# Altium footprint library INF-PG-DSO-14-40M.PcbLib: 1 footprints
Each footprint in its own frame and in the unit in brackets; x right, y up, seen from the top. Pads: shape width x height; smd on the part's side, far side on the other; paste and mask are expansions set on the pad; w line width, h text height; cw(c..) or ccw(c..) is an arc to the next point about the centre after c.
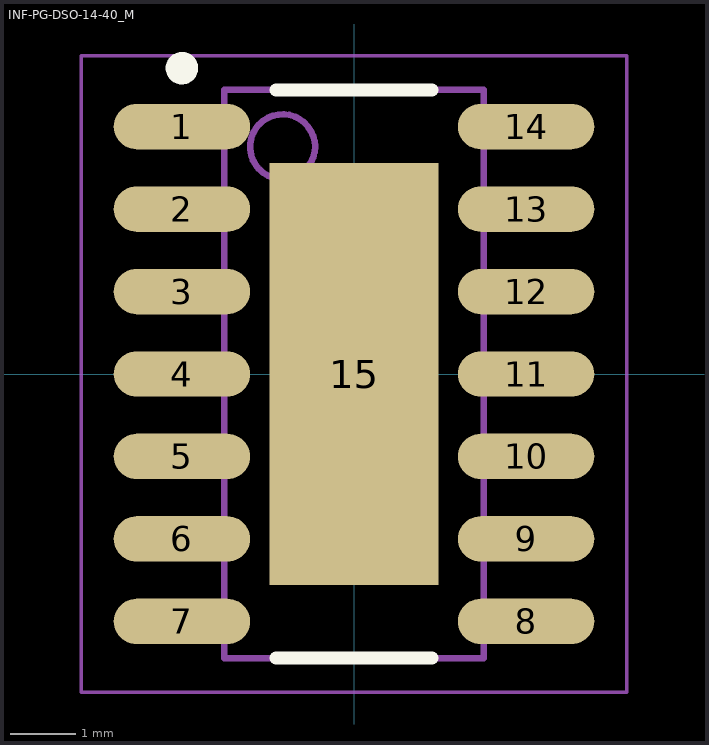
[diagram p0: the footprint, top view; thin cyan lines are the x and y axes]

## INF-PG-DSO-14-40_M [mm] "SOP, 14-Leads, Body 8.65x3.9mm, Pitch 1.27mm, Thermal Pad 6.5x2.6mm, IPC Low Density"
height 1.7
pads (15):
  oval 2.1x0.7 smd: 1(-2.65,3.81) 2(-2.65,2.54) 3(-2.65,1.27) 4(-2.65,0) 5(-2.65,-1.27) 6(-2.65,-2.54) 7(-2.65,-3.81) 8(2.65,-3.81) 9(2.65,-2.54) 10(2.65,-1.27) 11(2.65,0) 12(2.65,1.27) 13(2.65,2.54) 14(2.65,3.81)
  rect 2.6x6.5 smd: 15(0,0)
Top Overlay:
  circle w0.25: c-2.65,4.71 r0.125
  lines w0.2: -1.2,-4.375 1.2,-4.375 ; -1.2,4.375 1.2,4.375
Mechanical 13:
  circle w0.1: c-1.1,3.5 r0.5
  lines w0.1: -2,-4.375 -2,4.375 2,4.375 2,-4.375 -2,-4.375
Mechanical 15:
  lines w0.05: -4.2,-4.9 -4.2,4.9 4.2,4.9 4.2,-4.9 -4.2,-4.9
  lines w0.1: -0.5,0 0.5,0 ; 0,-0.5 0,0.5
3D body: height 1.7, standoff 0, extent -2,-4.375 2,4.375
